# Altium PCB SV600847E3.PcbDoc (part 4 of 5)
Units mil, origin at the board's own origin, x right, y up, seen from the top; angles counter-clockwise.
Board outline 5404 x 2680 mil, 10 copper layers (Top Layer L1, Gnd-Plane - L2, Signals - L3, Gnd-Plane - L4, Pwr Plane - L5, Signals - L6, Gnd-Plane - L7, Signals - L8, Gnd-Plane - L9, Bottom Layer - L10), stack 57.8 mil thick; 517 components, 320 nets, 1784 pads, 1289 vias.
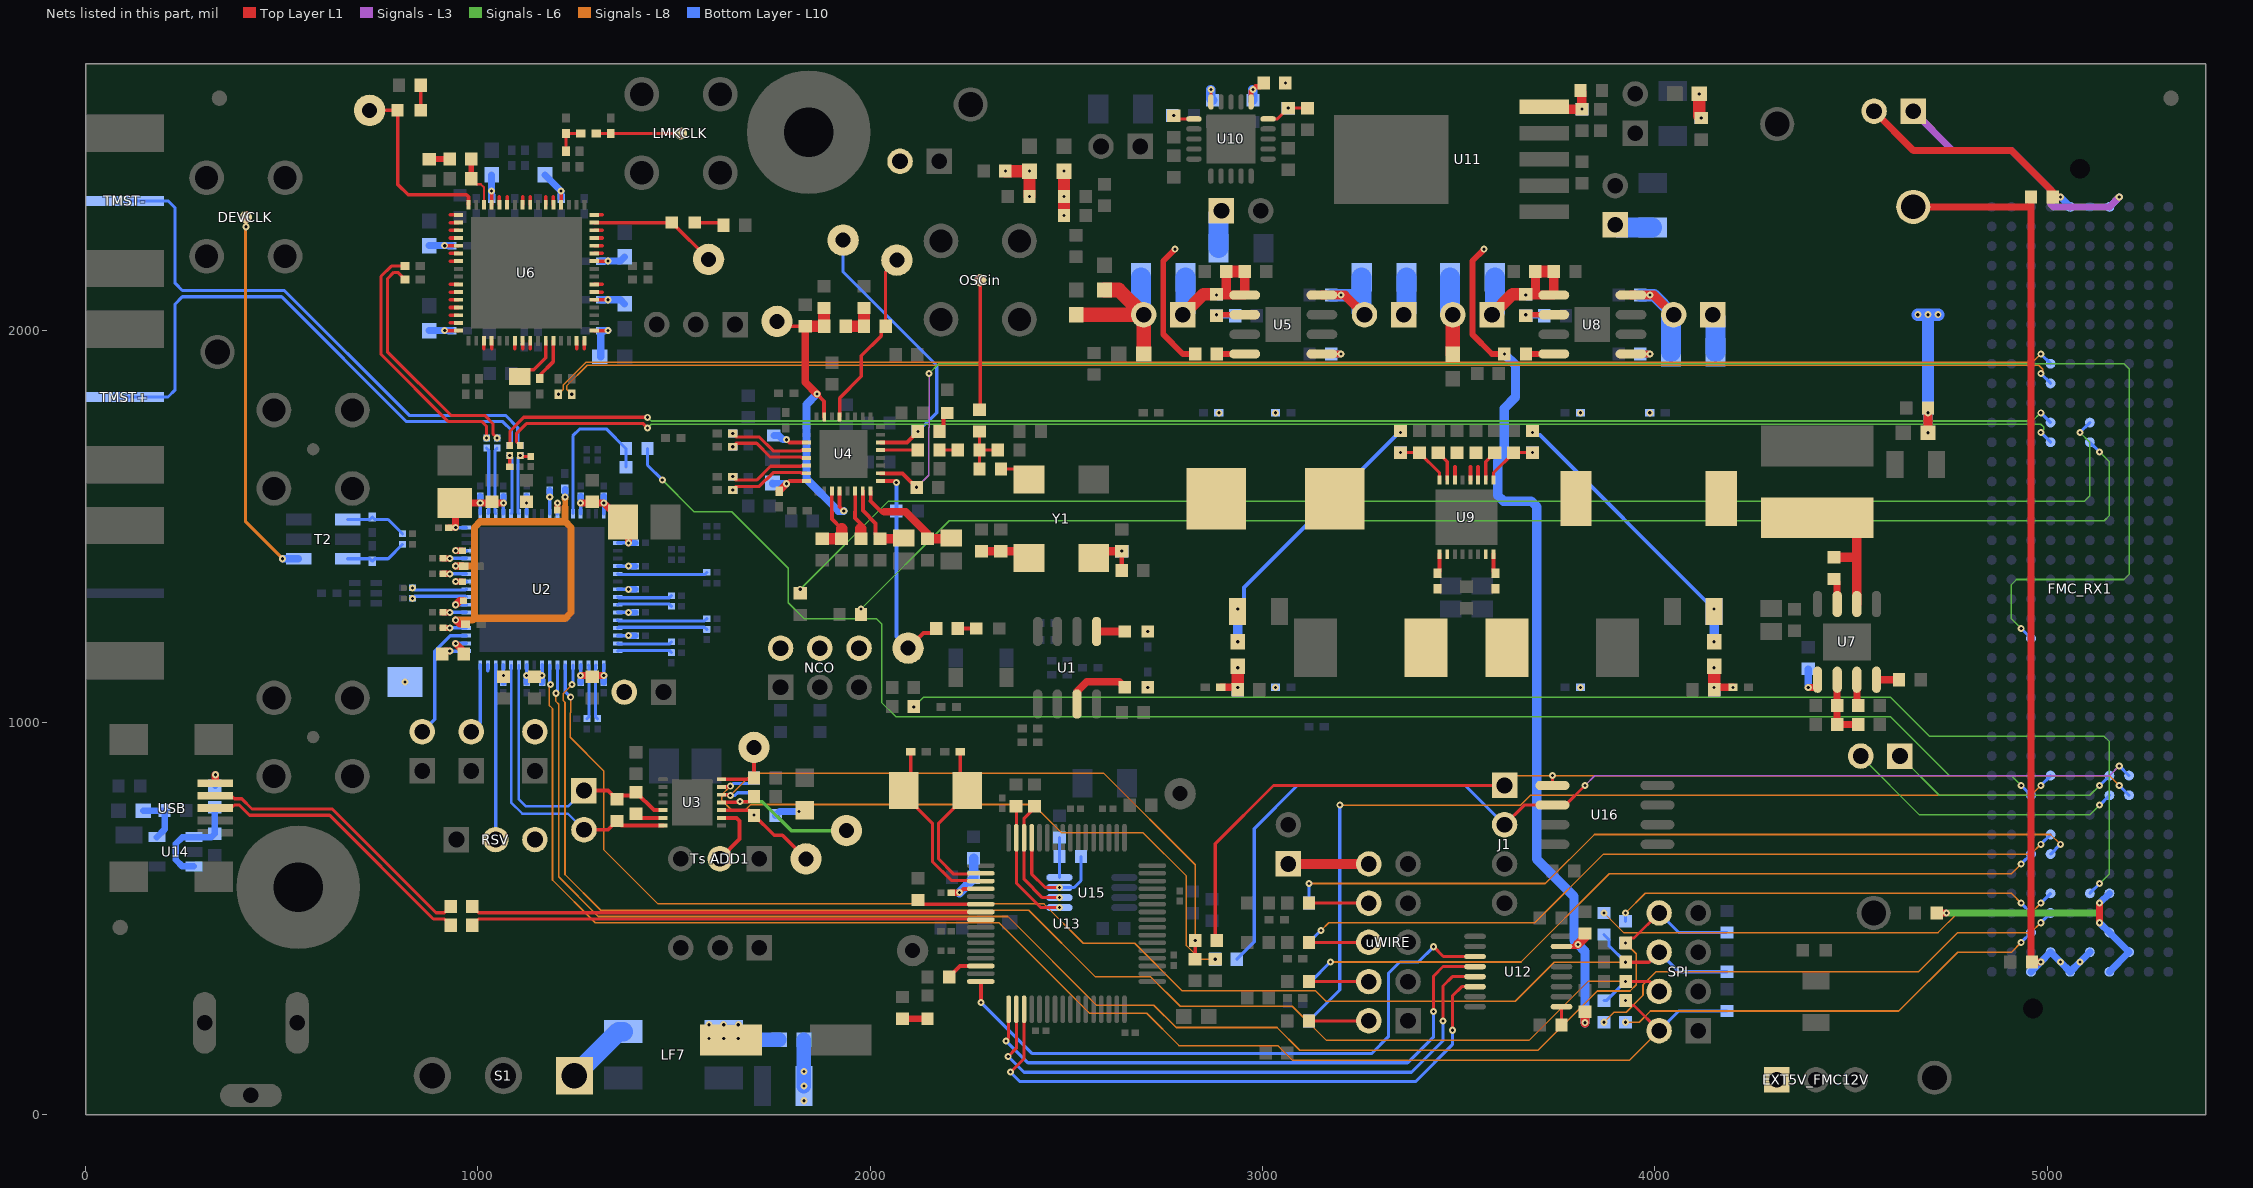
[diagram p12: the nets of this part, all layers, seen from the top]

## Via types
v1: diameter 18, hole 8, Top Layer L1 to Bottom Layer - L10, tented both sides, 1069 vias
v2: diameter 19.68, hole 7.87, Top Layer L1 to Bottom Layer - L10, 95 vias
v3: diameter 18, hole 8, Top Layer L1 to Bottom Layer - L10, tented bottom, 56 vias
v4: diameter 18, hole 8, Top Layer L1 to Bottom Layer - L10, tented top, 54 vias
v5: diameter 25.98, hole 12.99, Top Layer L1 to Bottom Layer - L10, tented top, 8 vias
v6: diameter 19.68, hole 7.87, Top Layer L1 to Bottom Layer - L10, tented top, 5 vias
v7: diameter 126, hole 106, Top Layer L1 to Bottom Layer - L10, tented top, 2 vias

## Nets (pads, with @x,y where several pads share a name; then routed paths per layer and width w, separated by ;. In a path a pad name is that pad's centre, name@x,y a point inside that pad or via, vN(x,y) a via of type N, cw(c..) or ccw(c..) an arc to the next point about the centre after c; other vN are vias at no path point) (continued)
NetC16_2: C16.2 C18.2 C19.2 U2.5 U2.12 U2.29 | length 1287.4
  Top Layer L1 w18: v1(943.26,1261.26) 953.31,1251.21 C18.2@968.57,1251.2 ; v1(943.26,1399.05) C19.2@963.52,1399.05
  Signals - L8 w13: 1222.44,1549.33 v1@1222.44,1570.92
  Signals - L8 w18: v1(943.26,1261.26) 986.22,1261.26 991.14,1266.18 ; v1(943.26,1399.05) 991.14,1399.05 ; 990.79,1497.48 1005.56,1512.24 1222.79,1512.24 ; 991.14,1497.83 991.14,1266.18 ; 1222.44,1549.33 1222.44,1512.59 1237.2,1497.83 1237.2,1280.6 1222.79,1266.18 991.14,1266.18 ; v1@1222.44,1570.92 v1(1222.44,1575.13)
  Bottom Layer - L10 w9: v1(943.26,1261.26) U2.5@970.47,1261.26 ; v1(943.26,1399.05) U2.12@970.47,1399.06 ; U2.29@1222.44,1532.91 v1(1222.44,1575.13)
  Bottom Layer - L10 w16: v1(1222.44,1575.13) C16.2@1222.44,1595.94
NetC17_2: C17.2 U2.41 | length 229.9
  Bottom Layer - L10 w8: U2.41@1356.3,1379.37 1358.14,1377.53 1577.7,1377.53 C17.2@1583.2,1383.03
NetC20_2: C20.2 U2.45 | length 139.9
  Bottom Layer - L10 w8: U2.45@1356.3,1300.63 1358.14,1302.47 1487.7,1302.47 C20.2@1493.2,1296.97
NetC21_2: C21.2 U2.44 | length 139.9
  Bottom Layer - L10 w8: U2.44@1356.3,1320.31 1358.14,1318.47 1487.7,1318.47 C21.2@1493.2,1323.97
NetC22_2: C22.2 R7.2 U2.48 | length 229.9
  Bottom Layer - L10 w8: U2.48@1356.3,1241.57 1358.14,1243.42 1577.7,1243.42 C22.2@1583.2,1237.92
NetC23_2: C23.2 U2.47 | length 229.9
  Bottom Layer - L10 w8: U2.47@1356.3,1261.26 1358.14,1259.42 1577.7,1259.42 C23.2@1583.2,1264.92
NetC26_2: C26.2 R8.2 U2.51 | length 139.9
  Bottom Layer - L10 w8: U2.51@1356.3,1182.52 1358.14,1184.36 1487.7,1184.36 C26.2@1493.2,1178.86
NetC28_2: C28.2 U2.50 | length 139.9
  Bottom Layer - L10 w8: U2.50@1356.3,1202.2 1358.14,1200.36 1487.7,1200.36 C28.2@1493.2,1205.86
NetC29_2: C29.2 R9.2 U2.54 | length 139.9
  Bottom Layer - L10 w8: C29.2@1277.84,1010.19 1283.34,1015.68 1283.34,1145.24 U2.54@1281.5,1147.09
NetC30_2: C30.2 C229.1 T2.4 | length 159.6
  Bottom Layer - L10 w8: T2.4@668.25,1417.95 724.67,1417.95 C229.1@730.85,1411.77 737.03,1417.95 771.09,1417.95 C30.2@807.59,1454.45
NetC31_2: C31.2 U2.53 | length 139.9
  Bottom Layer - L10 w8: U2.53@1301.18,1147.09 1299.34,1145.24 1299.34,1015.69 C31.2@1304.84,1010.19
NetC34_1: C34.1 U3.6 | length 72.4
  Top Layer L1 w10: C34.1@1403.28,767.44 1413.33,757.39 U3.6@1471.47,757.39
NetC34_2: C34.2 C38.2 Tdiode.1 U2.63 U3.5 | length 768.8
  Top Layer L1 w10: Tdiode.1@1270.28,827 1331.84,827 C38.2@1354.28,804.56 1363.72,814 1394.72,814 C34.2@1403.28,822.56 1448.76,777.07 U3.5@1471.47,777.07
  Bottom Layer - L10 w6: U2.63@1104.33,1147.09 1104.33,804.52 1121.5,787.34 1230.62,787.34 Tdiode.1@1270.28,827
NetC36_2: C36.2 C228.1 T2.6 | length 159.6
  Bottom Layer - L10 w8: T2.6@668.25,1517.95 724.67,1517.95 C228.1@730.85,1524.14 737.03,1517.95 771.09,1517.95 C36.2@807.59,1481.45
NetC38_1: C38.1 Tdiode.2 U2.64 U3.7 | length 780.4
  Top Layer L1 w10: Tdiode.2@1270.28,727 1331.84,727 C38.1@1354.28,749.44 1366.02,737.7 U3.7@1471.47,737.7
  Bottom Layer - L10 w6: U2.64@1084.65,1147.09 1084.65,796.36 1113.35,767.66 1229.62,767.66 Tdiode.2@1270.28,727
NetC73_1: C73.1 R24.2 Y1.4 | length 127.8
  Top Layer L1 w22: R24.2@2283.8,1437.44 C73.1@2332.8,1437.44 2386.88,1437.44 Y1.4@2404.32,1420
NetC74_2: C74.2 R26.2 R133.1 Y1.1 | length 126.2
  Top Layer L1 w12.5: R133.1@2641.2,1390 v1(2641.21,1437.44)
  Top Layer L1 w22: Y1.1@2569.68,1420 2587.12,1437.44 v1(2641.21,1437.44)
NetC79_1: C79.1 U4.29 | length 95.2
  Top Layer L1 w8: U4.29@2026.36,1694.8 C79.1@2121.58,1694.8
NetC79_2: C79.2 R29.2 | length 46.6
  Top Layer L1 w8: C79.2@2176.7,1694.8 R29.2@2223.26,1694.8
NetC80_2: C80.2 C81.1 U4.24 | length 273.8
  Top Layer L1 w9: 2000.77,1564.79 U4.24@2000.77,1590.47
  Top Layer L1 w10: 2000.77,1564.79 2029.81,1535.76
  Top Layer L1 w20: 2036.17,1537.88 2089.95,1537.88 2145.86,1481.98 C80.2@2145.86,1468.85
  Top Layer L1 w25: C80.2@2145.86,1468.85 2204.15,1468.85 C81.1@2206.12,1470.82
NetC82_2: C82.2 C83.1 U4.23 | length 201
  Top Layer L1 w10: U4.23@1981.09,1590.47 1981.09,1540.99 2013.9,1508.18 2013.9,1480.28 C82.2@2025.33,1468.85
  Top Layer L1 w25: C82.2@2025.33,1468.85 2083.62,1468.85 C83.1@2085.59,1470.82
NetC84_2: C84.2 U4.22 | length 127.7
  Top Layer L1 w9: 1961.4,1537.61 U4.22@1961.4,1590.47
  Top Layer L1 w10: 1961.4,1537.61 1961.4,1521.7 1976.07,1507.03 1976.07,1494.3
  Top Layer L1 w30: C84.2@1976.07,1468.85 1976.07,1494.3
NetC85_2: C85.2 C87.2 U4.19 | length 181.2
  Top Layer L1 w9: 1902.35,1537.61 U4.19@1902.35,1590.47
  Top Layer L1 w10: 1902.35,1537.61 1902.35,1519.19 1927.24,1494.3
  Top Layer L1 w30: C87.2@1877.54,1468.85 C85.2@1926.81,1468.85 ; C85.2@1927.24,1468.85 1927.24,1494.3
NetC86_1: C86.1 C90.1 C92.1 U4.7 U4.20 Vtune.1 | length 833.6
  Top Layer L1 w8: Vtune.1@1762.39,2023 1774.81,2010.58 C86.1@1834.31,2010.58
  Top Layer L1 w10: v1(1864.03,1838) 1882.66,1819.36 U4.7@1882.66,1779.45 ; U4.20@1922.03,1590.47 1922.03,1550.55 v1@1931.87,1540.71
  Top Layer L1 w20: C86.1@1834.31,2010.58 1834.31,1867.71 v1(1864.03,1838)
  Top Layer L1 w30: C86.1@1834.31,2010.58 C90.1@1882.39,2010.58 C92.1@1882.39,2057.25
  Bottom Layer - L10 w20: v1(1864.03,1838) 1837.39,1811.36 1837.39,1621.05 1918.44,1540 v1(1932.58,1540)
NetC90_2: C90.2 R33.1 R34.2 | length 93.3
  Top Layer L1 w30: C90.2@1937.51,2010.58 R34.2@1984.18,2010.58 R33.1@1984.18,2057.25
NetC93_1: C93.1 U4.11 | length 90.5
  Top Layer L1 w10: v1(1786.92,1721.41) 1793.84,1714.48 U4.11@1837.39,1714.48
  Bottom Layer - L10 w18: C93.1@1754.18,1732.16 1766.84,1732.16 1777.59,1721.41 v1(1786.92,1721.41)
NetC117_1: C117.1 C126.1 C166.1 LMK_LDO.1 R40.1 R41.2 U5.5 | length 443.2
  Top Layer L1 w23.5: C117.1@2883,2092.56 2885.56,2090 U5.5@2954.57,2090 C126.1@2954.57,2150 ; 2907.56,2090 C166.1@2907.56,2150
  Top Layer L1 w31.5: LMK_LDO.1@2797,2040 2849.56,2092.56 C117.1@2880.44,2092.56 ; C166.1@2907.56,2150 C126.1@2954.57,2150
  Bottom Layer - L10 w51: LMK_LDO.1@2797,2040 2804.09,2047.09 R40.1@2804.09,2135.44
  other v1: 2883,2090
NetC117_2: C117.2 R41.1 R49.2 U5.6 | length 120.1
  Top Layer L1 w15: C117.2@2883,2037.44 2885.56,2040 U5.6@2954.57,2040
  Bottom Layer - L10 w15: R41.1@2883,2037.44 R49.2@2930.44,2037.44
  other v1: 2883,2040
NetC122_1: C122.1 U6.11 | length 129.3
  Top Layer L1 w9: C122.1@1106.9,1882.27 1124.37,1899.74 1142.3,1899.74 1172.77,1930.21 U6.11@1172.77,1973.77
NetC123_2: C123.2 R48.1 R50.1 | length 82.6
  Top Layer L1 w8: C123.2@1224.67,2456.69 R50.1@1224.67,2502 R48.1@1261.98,2502
NetC124_1: C124.1 U6.12 | length 110.9
  Top Layer L1 w9: C124.1@1157.3,1877.43 1157.3,1885.74 1192.46,1920.9 U6.12@1192.46,1973.77
NetC127_1: C127.1 LMK_INT.2 R42.2 U5.4 | length 304.5
  Top Layer L1 w23.5: U5.4@3151.43,2090 v1(3199.79,2090) 3210,2090 LMK_INT.2@3260,2040
  Bottom Layer - L10 w31.5: C127.1@3175.05,2090 v1(3199.79,2090) 3252.91,2090
  Bottom Layer - L10 w51: R42.2@3252.91,2134.44 3252.91,2047.09 LMK_INT.2@3260,2040
NetC128_1: C128.1 U5.1 | length 73.1
  Top Layer L1 w18: U5.1@3151.43,1940 v1(3199.8,1940)
  Bottom Layer - L10 w18: C128.1@3175.05,1940 v1(3199.8,1940)
NetC135_1: C135.1 U13.2 Y2.1 | length 435
  Top Layer L1 w8: C135.1@2229.65,926 2229.65,844.53 Y2.1@2247.18,827 2247.18,816.71 2174.47,744 2174.47,652.63 2212.99,614.11 2247.63,614.11 2249.47,615.95 U13.2@2281.97,615.95
NetC137_1: C137.1 U13.3 Y2.2 | length 461.5
  Top Layer L1 w8: C137.1@2103.29,926 2103.29,844.53 Y2.2@2085.76,827 2085.76,816.71 2158.47,744 2158.47,646 2206.36,598.11 2247.63,598.11 2249.47,596.27 U13.3@2281.97,596.27
NetC141_1: C141.1 C142.1 L25.2 U13.4 | length 182.2
  Top Layer L1 w10: v1(2227.5,566.74) 2237.34,576.58 U13.4@2281.97,576.58
  Top Layer L1 w16.5: C142.1@2206.44,566.74 v1(2227.5,566.74)
  Bottom Layer - L10 w24: v1(2227.5,566.74) 2263.56,602.8 C141.1@2263.56,606 L25.2@2263.56,654.44
NetC148_1: C148.1 L8.1 U7.6 | length 378.7
  Top Layer L1 w23.62: L8.1@4414,1522.46 4515,1522.46 U7.6@4515,1302.46 ; C148.1@4457.27,1421.56 4515,1421.56
NetC148_2: C148.2 U7.7 | length 67.2
  Top Layer L1 w18: C148.2@4457.27,1366.44 4465,1358.71 U7.7@4465,1302.46
NetC149_1: C149.1 C150.1 C151.1 LMX_LDO.1 R73.1 R74.2 U8.5 | length 442.2
  Top Layer L1 w23.5: C149.1@3671,2092.56 3673.56,2090 U8.5@3742.57,2090 C151.1@3742.57,2150 ; 3695.56,2090 C150.1@3695.56,2150
  Top Layer L1 w31.5: LMX_LDO.1@3585,2040 3637.56,2092.56 C149.1@3668.44,2092.56 ; C150.1@3695.56,2150 C151.1@3742.57,2150
  Bottom Layer - L10 w51: LMX_LDO.1@3585,2040 3592.09,2047.09 R73.1@3592.09,2134.44
  other v1: 3671,2090
NetC149_2: C149.2 R74.1 R77.2 U8.6 | length 120.1
  Top Layer L1 w15: C149.2@3671,2037.44 3673.56,2040 U8.6@3742.57,2040
  Bottom Layer - L10 w15: R74.1@3671,2037.44 R77.2@3718.44,2037.44
  other v1: 3671,2040
NetC154_1: C154.1 R72.2 R76.2 U7.2 | length 168
  Top Layer L1 w18: U7.2@4465,1109.54 R72.2@4465,995 R76.2@4518.44,995
NetC155_1: C155.1 U7.3 | length 65.5
  Top Layer L1 w18: C155.1@4515,1044 U7.3@4515,1109.54
NetC158_1: C158.1 C159.1 L7.2 LMK_INT.1 LMX_INT.1 R42.1 R75.1 | length 610.3
  Top Layer L1 w24: v1(4696.5,1739.21) C159.1@4696.5,1802
  Bottom Layer - L10 w24: v1(4696.5,1739.21) C158.1@4696.5,1802
  Bottom Layer - L10 w31.5: v1(4670.5,2040) v1(4722.5,2040) ; C158.1@4696.5,1802 v1(4696.5,2040)
  Bottom Layer - L10 w51: LMK_INT.1@3360,2040 3367.09,2047.09 R42.1@3367.09,2134.44 ; LMX_INT.1@4148,2040 4155.09,2032.91 R75.1@4155.09,1945.56
  other v1: 4696.5,1790
NetC160_1: C160.1 LMX_INT.2 R75.2 U8.4 | length 332.3
  Top Layer L1 w23.5: U8.4@3939.43,2090 v1(3987.79,2090) 3998,2090 LMX_INT.2@4048,2040
  Bottom Layer - L10 w31.5: C160.1@3963.05,2090 v1(3987.79,2090) 3998,2090 LMX_INT.2@4048,2040
  Bottom Layer - L10 w51: R75.2@4040.91,1945.56 4040.91,2032.91 LMX_INT.2@4048,2040
NetC161_1: C161.1 U8.1 | length 73.1
  Top Layer L1 w18: U8.1@3939.43,1940 v1(3987.8,1940)
  Bottom Layer - L10 w18: C161.1@3963.05,1940 v1(3987.8,1940)
NetC162_1: C162.1 U7.4 | length 57.4
  Top Layer L1 w18: U7.4@4565,1109.54 C162.1@4622.44,1109.54
NetC168_1: C168.1 R78.2 U9.3 U9.4 U9.6 | length 100.5
  Top Layer L1 w10: U9.6@3490.47,1618.49 3490.47,1652 ; U9.4@3529.84,1618.49 3529.84,1652 ; U9.3@3549.53,1618.49 3549.53,1652
NetC169_1: C169.1 U9.16 | length 50.8
  Top Layer L1 w10: U9.16@3588.9,1429.51 3588.9,1385.53 C169.1@3593.74,1380.68
NetC169_2: C169.2 D11.1 L11.2 U9.15
NetC170_1: C170.1 D12.1 L12.1 U9.10
NetC170_2: C170.2 U9.9 | length 50.8
  Top Layer L1 w10: C170.2@3446.26,1380.69 3451.1,1385.53 U9.9@3451.1,1429.51
NetC174_1: C174.1 R81.2 R86.2 U9.1 | length 139.1
  Top Layer L1 w8: U9.1@3588.9,1618.49 3588.9,1637.34 R86.2@3640,1688.44 v1(3688,1688.44)
NetC175_2: C175.2 R82.1 R87.2 U9.8 | length 139.1
  Top Layer L1 w8: v1(3352,1688.44) R87.2@3400,1688.44 3451.1,1637.34 U9.8@3451.1,1618.49
NetC178_1: C178.1 U9.2 | length 79.4
  Top Layer L1 w8: U9.2@3569.21,1618.49 3569.21,1665.65 C178.1@3592,1688.44
NetC179_1: C179.1 U9.7 | length 79.4
  Top Layer L1 w8: C179.1@3448,1688.44 3470.79,1665.65 U9.7@3470.79,1618.49
NetC186_1: C186.1 R79.1 R90.2 U10.10 | length 111.9
  Top Layer L1 w8: U10.10@3014.16,2539.18 3038.3,2539.18 v1(3065.68,2566.56) R79.1@3114.68,2566.56
NetC187_1: C187.1 U10.15 | length 61.2
  Top Layer L1 w8: U10.15@2868.49,2582.49 v1(2868.49,2614.17)
  Bottom Layer - L10 w24: v1(2868.49,2614.17) 2868.49,2590.61 C187.1@2872.67,2586.43
NetC192_2: C192.2 R93.1 R96.2 U11.5 | length 147.7
  Top Layer L1 w24: U11.5@3718.22,2569.86 3724.13,2563.95 v1(3814,2563.95) 3814,2608.44 R96.2@3810.44,2612
NetC193_1: C193.1 L17.1 LF7.3 | length 150.4
  Bottom Layer - L10 w37: LF7.3@1626.46,212.6 1657.4,212.6 1678.4,191.6 L17.1@1768.16,191.6
  other v1: 1589.24,195.07 1626.46,195.07 1663.67,195.07 1589.24,230.12 1626.46,230.12 1663.67,230.12
NetC194_1: C194.1 EXT5V_FMC12V.1 L17.2 | length 118.1
  Bottom Layer - L10 w37: v1(1831.15,73.49) L17.2@1831.15,191.6
  other v1: 1831.15,36.28 1831.15,110.7
NetC201_1: C201.1 R103.2 U14.1 U14.3 | length 271.6
  Bottom Layer - L10 w16.5: U14.3@275.94,633.46 246.64,633.46 229.76,650.33 229.76,691.39 246.64,708.26 U14.1@275.94,708.26 320.38,708.26 C201.1@329.24,717.12 R103.2@329.24,784.4
NetC211_1: C211.1 L26.1 U14.5 | length 130.2
  Bottom Layer - L10 w16.5: L26.1@146.73,775.86 C211.1@201.14,775.86 201.14,727.95 U14.5@181.46,708.26
NetC213_2: C213.2 L1.2 U4.16 | length 118.1
  Top Layer L1 w10: v1(1786.92,1609.14) 1793.84,1616.06 U4.16@1837.39,1616.06
  Top Layer L1 w18: C213.2@1767.87,1590.09 v1(1786.92,1609.14)
  Bottom Layer - L10 w18: L1.2@1751,1611 1751,1609.14 v1(1786.92,1609.14)
NetDEVCLK_1: DEVCLK.1 T2.3 | length 951.6
  Top Layer L1 w8: v1(408.31,2264.25) DEVCLK.1@408.31,2289
  Signals - L8 w8: v1@407.71,2264.25 407.71,1512.24 v1@502,1417.95
  Bottom Layer - L10 w18: v1(501.57,1417.95) T2.3@543.06,1417.95
NetFLout_1: FLout.1 R34.1 U4.5 | length 459.7
  Top Layer L1 w8: R34.1@2039.3,2010.58 2039.3,2150.3 FLout.1@2068,2179
  Top Layer L1 w9: U4.5@1922.03,1779.8 1922.03,1827.59 1977.48,1883.04 1977.48,1935.36 2028.04,1985.92 2028.04,1999.32 R34.1@2039.3,2010.58
NetFMC_RX1_C30: FMC_RX1.C30 J1.2 R127.2 U16.6 | length 2740.7
  Top Layer L1 w8: J1.2@3617,740 3667,790 U16.6@3739.14,790 3772.2,790 v1(3822.2,840)
  Signals - L3 w4: v1(3822.2,840) 3847.2,865 5159,865 v3(5184,890)
  Bottom Layer - L10 w8: R127.2@2934.68,397.13 2979,441.45 2979,730 3089,840 3517,840 J1.2@3617,740 ; v3(5184,890) FMC_RX1.C30@5209,865
NetFMC_RX1_C31: FMC_RX1.C31 J1.1 R126.2 U16.5 | length 2693.6
  Top Layer L1 w8: R126.2@2879.56,445 2879.56,691.56 3028,840 J1.1@3617,840 ; U16.5@3739.14,840 v1(3739.14,865)
  Signals - L8 w4: J1.1@3617,840 3642,865 5159,865 v3(5184,840)
  Bottom Layer - L10 w8: v3(5184,840) FMC_RX1.C31@5209,815
NetFMC_RX1_C39: FMC_RX1.C39 FMC_RX1.D36 FMC_RX1.D38 FMC_RX1.D40 R132.2 | length 727.6
  Top Layer L1 w18: R132.2@4718.56,515 v1(4743.31,515) ; v1(5134,490) v1(5134,540)
  Signals - L6 w18: v1(4743.31,515) 5134,515 ; v1(5134,490) v1(5134,540)
  Bottom Layer - L10 w18: v1(5134,490) FMC_RX1.D38@5159,465 FMC_RX1.C39@5209,415 FMC_RX1.D40@5159,365 ; v1(5134,540) FMC_RX1.D36@5159,565
NetFMC_RX1_D30: "KC705 JTAG.1" FMC_RX1.D30 | length 596.1
  Signals - L6 w4: 4625,915 4725,815 5109,815 v3(5134,840)
  Bottom Layer - L10 w8: v3(5134,840) FMC_RX1.D30@5159,865
NetFMC_RX1_D31: "KC705 JTAG.2" FMC_RX1.D31 | length 716.8
  Signals - L6 w4: 4525,915 4675,765 5109,765 v3(5134,790)
  Bottom Layer - L10 w8: v3(5134,790) FMC_RX1.D31@5159,815
NetFMC_RX1_E12: FMC_RX1.E12 R136.2 | length 3593.8
  Signals - L6 w4: v1(1821.5,1340) 2046.5,1565 5096,1565 5109,1578 5109,1715 v3(5084,1740)
  Bottom Layer - L10 w8: v3(5084,1740) FMC_RX1.E12@5109,1765
NetFMC_RX1_E13: FMC_RX1.E13 R137.2 | length 3488.7
  Signals - L6 w4: v1(1976.62,1290) 2201.62,1515 5146,1515 5159,1528 5159,1665 v3(5134,1690)
  Bottom Layer - L10 w8: FMC_RX1.E13@5109,1715 v3(5134,1690)
NetFMC_RX1_E36: FMC_RX1.E36 R138.2 | length 3512.8
  Signals - L6 w4: v1(2111.06,1040) 2136.06,1065 4601,1065 4701,965 5146,965 5159,952 5159,615 v3(5134,590)
  Bottom Layer - L10 w8: FMC_RX1.E36@5109,565 v3(5134,590)
NetFMC_RX1_G30: FMC_RX1.G30 R121.2 | length 2425
  Signals - L8 w4: v1@3197.99,789.01 3657.01,789.01 3683,815 4959,815 v3(4984,840)
  Bottom Layer - L10 w8: R121.2@3118.56,240 3197,318.44 v1(3197,790) ; v3(4984,840) FMC_RX1.G30@5009,865
NetFMC_RX1_G33: FMC_RX1.G33 R69.2 | length 2004.3
  Signals - L8 w4: v1(3149,470.44) 3168.56,490 3694,490 3869,665 4959,665 v3(4984,690)
  Bottom Layer - L10 w8: R69.2@3118.56,440 v1(3149,470.44) ; v3(4984,690) FMC_RX1.G33@5009,715
NetFMC_RX1_G34: FMC_RX1.G34 R119.2 | length 2062.9
  Signals - L8 w4: v1(3118.56,590) 3721,590 3846,715 5009,715 v3(5034,690)
  Bottom Layer - L10 w8: R119.2@3118.56,540 v1(3118.56,590) ; FMC_RX1.G34@5009,665 v3(5034,690)
NetFMC_RX1_G36: FMC_RX1.G36 R57.2 | length 1200.7
  Signals - L8 w4: v1(3870.44,515) 3920.44,465 4722,465 4772,515 4959,515 v3(4984,540)
  Bottom Layer - L10 w8: v3(4984,540) FMC_RX1.G36@5009,565
NetFMC_RX1_G37: FMC_RX1.G37 R55.2 | length 1269.8
  Signals - L8 w4: v1(3870.44,236.38) 3896.06,262 3927,262 3970,305 3970,332 4003,365 4672,365 4772,465 4959,465 v3(4984,490)
  Bottom Layer - L10 w8: v3(4984,490) FMC_RX1.G37@5009,515
NetFMC_RX1_H23: FMC_RX1.H23 R46.1 U4.26 | length 4477.4
  Top Layer L1 w10: U4.26@2026.36,1635.74 2082.5,1635.74 2086.5,1631.74 v1(2118.23,1600.02)
  Signals - L3 w4: v1(2118.23,1600.02) 2149.14,1630.92 2149.14,1752.14 2151,1754 v1@2151,1890
  Signals - L6 w4: v1(2150,1890) 2175,1915 5196,1915 5209,1902 5209,1378 5196,1365 4922,1365 4909,1352 4909,1265 v3(4934,1240)
  Bottom Layer - L10 w8: v3(4934,1240) FMC_RX1.H23@4959,1215
NetFMC_RX1_H34: FMC_RX1.H34 R120.2 | length 1975.1
  Signals - L8 w4: v1(3173,390) 3659,390 3884,615 4909,615 v3(4934,640)
  Bottom Layer - L10 w8: R120.2@3118.56,340 3123,340 v1(3173,390) ; v3(4934,640) FMC_RX1.H34@4959,665
NetFMC_RX1_H37: FMC_RX1.H37 R58.2 | length 1096.2
  Signals - L8 w4: v1(3925.56,515) 3975.56,565 4909,565 v3(4934,540)
  Bottom Layer - L10 w8: R58.2@3925.56,493.62 v1(3925.56,515) ; v3(4934,540) FMC_RX1.H37@4959,515
NetFMC_RX1_H38: FMC_RX1.H38 R54.2 | length 1128.1
  Signals - L8 w4: v1(3925.56,236.38) 3960.38,236.38 3989,265 4622,265 4772,415 4909,415 v3(4934,440)
  Bottom Layer - L10 w8: v3(4934,440) FMC_RX1.H38@4959,465
NetJ3_1: J3.1 uWIRE.10 | length 205
  Top Layer L1 w25: J3.1@3066,640 uWIRE.10@3271,640
NetL6_1: L6.1 LMX_LDO.2 R73.2 | length 197.9
  Top Layer L1 w37: L6.1@3485,1939.5 LMX_LDO.2@3485,2040
  Bottom Layer - L10 w51: R73.2@3477.91,2134.44 3477.91,2047.09 LMX_LDO.2@3485,2040
NetL9_1: L9.1 L10.1 L13.1 LMK_LDO.2 R40.2 | length 496.5
  Top Layer L1 w37: L13.1@2525,2040 LMK_LDO.2@2697,2040 ; L10.1@2597,2103 2634,2103 LMK_LDO.2@2697,2040 ; L9.1@2697,1940 LMK_LDO.2@2697,2040
  Bottom Layer - L10 w51: R40.2@2689.91,2135.44 2689.91,2047.09 LMK_LDO.2@2697,2040
NetLD1_1: LD1.1 Status1.1 U6.31 | length 330.1
  Top Layer L1 w9: U6.31@1296.79,2274.95 Status1.1@1493.98,2274.95 LD1.1@1587.93,2181
NetLD2_1: LD2.1 Status2.1 U6.48 | length 473.5
  Top Layer L1 w9: LD2.1@724,2561 Status2.1@794.71,2561 ; Status2.1@795,2561 795,2373 822,2346 970.65,2346 975.92,2340.73 U6.48@975.92,2320.23
NetLD_1: LD.1 R100.2 | length 46.9
  Top Layer L1 w10: R100.2@2223.06,1240 LD.1@2269.98,1240
NetLF1_1: LF1.1 LF2.1 U6.46 | length 136.1
  Top Layer L1 w5.5: LF2.1@982.86,2386.74 996.86,2372.74 1007.3,2372.74 1015.29,2364.75 U6.46@1015.29,2320.23
  Top Layer L1 w15: LF2.1@982.86,2386.74 LF1.1@982.86,2436.74
NetLF1_2: LF1.2 LF3.2 | length 51.9
  Top Layer L1 w15: LF3.2@875.86,2436.74 LF1.2@927.74,2436.74
NetLF7_2: LF7.2 S1.1 | length 171
  Bottom Layer - L10 w50: S1.1@1246.1,100.2 1358.5,212.6 LF7.2@1370.55,212.6
NetLMKCLK_1: LMKCLK.1 R48.2 R51.2 | length 216.1
  Top Layer L1 w8: R48.2@1301.36,2502 R51.2@1338.67,2502 LMKCLK.1@1517.5,2502
NetMUX_1: MUX.1 R99.1 R143.1 U4.30 | length 713.1
  Top Layer L1 w10: U4.30@2026.36,1714.48 2093.87,1714.48 v1(2121.58,1742.19)
  Bottom Layer - L10 w8: MUX.1@1931,2230 1931,2149 2169.5,1910.5 2169.5,1790.12 v1(2121.58,1742.19)
NetMUXout_1: MUXout.1 R99.2 | length 55.5
  Top Layer L1 w10: R99.2@2176.7,1742.19 2186.5,1752 2186.5,1779.47 MUXout.1@2196.5,1789.47
NetOR_T0_1: OR_T0.1 U1.1 | length 71.5
  Top Layer L1 w19.5: U1.1@2577,1232.52 OR_T0.1@2648.47,1232.52
NetOR_T0_2: OR_T0.2 R2.1
  other v1: 2707.53,1232.52
NetOR_T1_1: OR_T1.1 U1.7 | length 169.1
  Top Layer L1 w19.5: U1.7@2527,1047.48 2527,1079 2552,1104 2634.47,1104 OR_T1.1@2648.47,1090
NetOR_T1_2: OR_T1.2 R10.1
  other v1: 2707.53,1090
NetOSCin_1: OSCin.1 R25.2 | length 323.6
  Top Layer L1 w8: R25.2@2280.38,1804.45 OSCin.1@2280.38,2128
NetR13_1: R13.1 U2.2 | length 62.9
  Top Layer L1 w18: v1(943.26,1202.2) 963.82,1181.65 R13.1@963.82,1175
  Bottom Layer - L10 w9: v1(943.26,1202.2) U2.2@970.47,1202.2
NetR13_2: R13.2 U2.1 | length 64.9
  Top Layer L1 w18: R13.2@908.7,1175 916.22,1182.52 v1(928.26,1182.52)
  Bottom Layer - L10 w9: v1(928.26,1182.52) U2.1@970.47,1182.52
NetR17_2: R17.2 TEMP.2 | length 63.6
  Bottom Layer - L10 w18: R17.2@1758.84,763.41 1768.84,773.41 v1(1818.28,773.41)
NetR25_1: R25.1 R27.1 R28.2 R29.1 | length 142.8
  Top Layer L1 w8: R27.1@2278.38,1646.56 R29.1@2278.38,1694.8 ; R25.1@2278.38,1742.44 R29.1@2278.38,1694.8 ; R28.2@2325.26,1694.8 R29.1@2278.38,1694.8
NetR27_2: R27.2 Y1.3 | length 81.8
  Top Layer L1 w8: R27.2@2333.5,1646.56 2377.76,1646.56 Y1.3@2404.32,1620
NetR31_1: R31.1 R124.1 R126.1 U3.12 | length 1637
  Top Layer L1 w8: R124.1@2828,397.13 2828.44,397.57 v1(2828.44,445)
  Top Layer L1 w9: U3.12@1621.08,816.44 1641.28,816.44 v1(1643.28,814.44)
  Signals - L8 w4: v1(1643.28,814.44) 1700.46,871.62 2594.38,871.62 2828.44,637.56 v1(2828.44,445)
  Bottom Layer - L10 w8: v1(1643.28,814.44) 1654.96,814.44 1661.99,821.47 1693.66,821.47 R31.1@1703.72,811.41
NetR32_1: R32.1 R125.1 R127.1 U3.13 | length 1677.8
  Top Layer L1 w9: U3.13@1621.08,836.13 1641.28,836.13 v1(1643.28,838.13)
  Signals - L8 w4: v1(1643.28,838.13) 1621.08,815.93 1621.08,802.92 1646,778 1682,778 1695.44,791.44 2415.89,791.44 2488.33,719 2696,719 2806,609 2806,432 2840.87,397.13 v1(2879.56,397.13)
  Bottom Layer - L10 w8: v1(1643.28,838.13) 1650.15,845 1689.91,845 R32.1@1703.72,858.81
NetR39_2: R39.2 U5.8 | length 71
  Top Layer L1 w15: R39.2@2883.56,1940 U5.8@2954.57,1940
NetR45_2: R45.2 Status2.2 | length 63.7
  Top Layer L1 w9: Status2.2@854.05,2561.29 R45.2@854.06,2625
NetR52_1: R52.1 USB.2 | length 729.7
  Top Layer L1 w8: USB.2@330.71,813.93 371.71,813.93 379.46,806.18 397.98,806.18 424.17,780 628.63,780 892.94,515.69 914.24,515.69 R52.1@930.24,531.69
NetR52_2: R52.2 U13.7 | length 1304
  Top Layer L1 w8: R52.2@985.36,531.69 1001.36,515.69 2247.63,515.69 2249.47,517.53 U13.7@2281.97,517.53
NetR53_1: R53.1 USB.3 | length 729.7
  Top Layer L1 w8: USB.3@330.71,782.44 371.71,782.44 379.46,790.18 391.36,790.18 417.54,764 622,764 886.31,499.69 914.24,499.69 R53.1@930.24,483.69
NetR53_2: R53.2 U13.8 | length 1304
  Top Layer L1 w8: R53.2@985.36,483.69 1001.36,499.69 2247.63,499.69 2249.47,497.84 U13.8@2281.97,497.84
NetR54_1: R54.1 R118.1 R139.2 SPI.2 U2.59 | length 3907.1
  Top Layer L1 w8: v1(3925.56,291.5) 3938.06,279 3947,279 SPI.2@4011,215
  Signals - L8 w4: v1(1185.19,1097) 1182,1093.81 1182,1044 1190,1036 1190,599 1299,490 2328,490 2559,259 2705,259 2787,177 3039,177 3076,140 3936,140 SPI.2@4011,215
  Bottom Layer - L10 w8: U2.59@1183.07,1147.09 1183.07,1099.12 v1(1185.19,1097) ; SPI.2@4011,215 4061,265 R139.2@4184.44,265
NetR55_1: R55.1 R110.1 SPI.4 U2.56 | length 3659.1
  Top Layer L1 w8: v1(3925.56,340.5) 3985.5,340.5 SPI.4@4011,315
  Signals - L8 w4: v1(1240,1097) 1217,1074 1217,1057 1222,1052 1222,613 1313,522 2404,522 2574,352 2715,352 2790,277 3076,277 3163,190 3679.36,190 3829.86,340.5 v1(3925.56,340.5)
  Bottom Layer - L10 w8: v1(1240,1097) 1242.13,1099.12 U2.56@1242.13,1147.09 ; R55.1@3870.44,291.5 3876.56,291.5 v1(3925.56,340.5)
NetR56_2: R56.2 Status1.2 | length 72.9
  Top Layer L1 w9: Status1.2@1553.03,2274.95 R56.2@1625.94,2274.95
NetR57_1: R57.1 R111.1 R140.2 SPI.6 U2.57 | length 3702.1
  Top Layer L1 w8: v1(3925.56,389.5) 3985.5,389.5 SPI.6@4011,415
  Signals - L8 w4: v1(1236.44,1065) 1236.44,1026.44 1235,1025 1235,963 1320.28,877.72 1320.28,676.72 1459,538 2443,538 2543,438 2674,438 2795,317 3135,317 3162,290 3644,290 3743.5,389.5 v1(3925.56,389.5)
  Bottom Layer - L10 w8: U2.57@1222.44,1147.09 1222.44,1079 v1(1236.44,1065) ; R57.1@3870.44,459.88 3883,447.32 3883,432.06 v1(3925.56,389.5) ; SPI.6@4011,415 4061,365 R140.2@4184.44,365
NetR58_1: R58.1 R109.1 R141.2 SPI.8 U2.58 | length 3973.1
  Top Layer L1 w8: v1(3925.56,438.5) 3938.06,451 3947,451 SPI.8@4011,515
  Signals - L8 w4: v1(1198.76,1075) 1198.76,1054.24 1206,1047 1206,607 1307,506 2351,506 2577,280 2723,280 2780,223 3037,223 3095,165 3702,165 3853,316 3937,316 3953,332 3953,411.06 v1(3925.56,438.5)
  Bottom Layer - L10 w8: v1(1198.76,1075) 1202.76,1079 U2.58@1202.76,1147.09 ; SPI.8@4011,515 4061,465 R141.2@4184.44,465
NetR65_2: R65.2 U12.9 | length 47
  Top Layer L1 w8: R65.2@3762.24,229 U12.9@3762.24,275.96
NetR66_1: R66.1 U13.14 | length 92.5
  Top Layer L1 w10: R66.1@2201.03,351.73 2229.03,379.73 U13.14@2281.97,379.73
NetR67_2: R67.2 U13.6 | length 164.9
  Top Layer L1 w10: R67.2@2121.47,547.96 2132.22,537.21 U13.6@2281.97,537.21
NetR70_2: R70.2 U7.1 | length 71.1
  Top Layer L1 w18: v1(4391.19,1090) U7.1@4415,1090
  Bottom Layer - L10 w18: v1(4391.19,1090) R70.2@4391.19,1137.29
NetR71_2: R71.2 U8.8 | length 71
  Top Layer L1 w15: R71.2@3671.56,1940 U8.8@3742.57,1940
NetR80_2: R80.2 R89.2 U10.11 | length 96
  Top Layer L1 w13.5: U10.11@2970.86,2582.49 2970.86,2609.67 v1(2975.36,2614.17) 2982.18,2621 2993.1,2621 R80.2@3003.1,2631
  Bottom Layer - L10 w24: R89.2@2975.36,2586.43 v1(2975.36,2614.17)
NetR85_1: R85.1 R88.2 U10.16 | length 55
  Top Layer L1 w8: v1(2773.68,2547.56) 2782.05,2539.18 U10.16@2825.19,2539.18
NetR97_2: R97.2 uWIRE.8 | length 152.4
  Top Layer L1 w8: R97.2@3118.56,540 uWIRE.8@3271,540
NetR98_2: R98.2 uWIRE.6 | length 152.4
  Top Layer L1 w8: R98.2@3118.56,440 uWIRE.6@3271,440
NetR100_1: R100.1 R142.1 TP_LD.1 U4.25 | length 568.4
  Top Layer L1 w10: U4.25@2026.36,1616.06 2062.5,1616.06 v1(2066.5,1612.06) ; TP_LD.1@2096.5,1190 2135.5,1229 2156.94,1229 R100.1@2167.94,1240
  Bottom Layer - L10 w10: v1(2066.5,1612.06) 2066.5,1220 TP_LD.1@2096.5,1190
NetR101_2: R101.2 uWIRE.4 | length 152.4
  Top Layer L1 w8: R101.2@3118.56,340 uWIRE.4@3271,340
NetR102_2: R102.2 uWIRE.2 | length 152.4
  Top Layer L1 w8: R102.2@3118.56,240 uWIRE.2@3271,240
NetR103_1: R103.1 USB.1 | length 49.6
  Top Layer L1 w19.5: USB.1@330.71,845.43 v1(330.71,867.27)
  Bottom Layer - L10 w16.5: R103.1@330.71,839.52 v1(330.71,867.27)
NetR105_1: R105.1 R108.2 U15.4 | length 102.1
  Bottom Layer - L10 w8: U15.4@2482.32,605.39 R108.2@2482.32,659 R105.1@2482.32,707.44
NetR106_1: R106.1 U13.62 U15.2 | length 307.2
  Top Layer L1 w8: R106.1@2419.2,787.44 2419.2,783.44 2392.2,756.44 U13.62@2392.2,706.5 2392.2,600.8 2438.8,554.2 v1(2482.32,554.2)
NetR107_1: R107.1 U13.63 U15.1 | length 332.3
  Top Layer L1 w8: R107.1@2371.2,787.44 2372.52,786.13 U13.63@2372.52,706.5 2372.52,591.48 2435.39,528.61 v1(2482.32,528.61)
NetR108_1: R108.1 U13.61 U15.3 | length 301
  Top Layer L1 w8: U13.61@2411.89,706.5 2411.89,614.11 2446.2,579.8 v1(2482.32,579.8)
  Bottom Layer - L10 w8: v1(2482.32,579.8) 2519.8,579.8 2537.44,597.44 R108.1@2537.44,659
NetR112_2: R112.2 USB_PWR.2 | length 64
  Top Layer L1 w16.5: R112.2@2081.91,245.68 USB_PWR.2@2145.91,245.68
NetR134_2: R134.2 R135.2 U2.30 | length 408.9
  Bottom Layer - L10 w8: U2.30@1242.13,1532.91 1242.13,1731.13 1260,1749 1327.24,1749 R134.2@1377.24,1699 R135.2@1377.24,1651.56
NetRSV_2: RSV.2 U2.66 | length 445.1
  Bottom Layer - L10 w9: RSV.2@1045.28,702 U2.66@1045.28,1147.09
"NetTs ADD1_2": "Ts ADD1.2" U3.9 | length 166.4
  Top Layer L1 w10: 1617.28,653 1667.28,703 1667.28,749 1658.89,757.39 U3.9@1621.08,757.39
NetU2_3: U2.3 Vcmo.2 | length 315.6
  Bottom Layer - L10 w9: Vcmo.2@857.78,977 890,1009.22 890,1182.5 929.39,1221.89 U2.3@970.47,1221.89
NetU2_68: U2.68 Vbg.2 | length 179.7
  Bottom Layer - L10 w9: Vbg.2@982.78,977 1005.91,1000.13 U2.68@1005.91,1147.09
NetU12_3: U12.3 U13.16 | length 1584.7
  Top Layer L1 w8: v1(3436.14,428.91) 3461.14,403.91 U12.3@3541.76,403.91
  Top Layer L1 w10: v1(2281.97,287) U13.16@2281.97,340.36
  Bottom Layer - L10 w8: v1(2281.97,287) 2411.97,157 3279,157 3321,199 3321,360.71 3350.29,390 3397.23,390 v1(3436.14,428.91)
NetU12_4: U12.4 U13.17 | length 1495
  Top Layer L1 w8: v1(2345.83,189.03) 2352.83,196.03 U13.17@2352.83,269.5 ; v1(3436.14,264) 3436.14,354.32 3460.14,378.32 U12.4@3541.76,378.32
  Bottom Layer - L10 w8: v1(2345.83,189.03) 2401.86,133 3370,133 3436.14,199.14 v1(3436.14,264)
NetU12_5: U12.5 U13.18 | length 1542.4
  Top Layer L1 w8: v1(2351.68,149.19) 2372.52,170.03 U13.18@2372.52,269.5 ; v1(3460.14,240) 3460.14,328.73 3484.14,352.73 U12.5@3565.76,352.73
  Bottom Layer - L10 w8: v1(2351.68,149.19) 2391.86,109 3379.94,109 3460.14,189.2 v1(3460.14,240)
NetU12_6: U12.6 U13.19 | length 1541.7
  Top Layer L1 w8: v1(2357.52,109.34) 2392.2,144.03 U13.19@2392.2,269.5 ; v1(3484.14,216) 3484.14,303.14 3508.14,327.14 U12.6@3541.76,327.14
  Bottom Layer - L10 w8: v1(2357.52,109.34) 2381.86,85 3389.88,85 3484.14,179.26 v1(3484.14,216)
PG_C2M_RX: FMC_RX1.D1 PG_RX1.1 | length 692.9
  Signals - L3 w18: PG_RX1.1@4659,2559 4759,2459 4909,2459 5009,2359 5009,2323 5017,2315 5159,2315 v3(5184,2340)
  Bottom Layer - L10 w18: FMC_RX1.D1@5159,2315 v3(5184,2340)
PG_M2C_RX: FMC_RX1.F1 PG_RX1.2 RR6.1 | length 609.2
  Top Layer L1 w18: PG_RX1.2@4559,2559 4659,2459 4909,2459 5014.12,2353.88 RR6.1@5014.12,2340 v1(5034,2340)
  Bottom Layer - L10 w18: v1(5034,2340) FMC_RX1.F1@5059,2315
RFOUTA_N: C96.1 R38.2 U4.13 | length 206.9
  Top Layer L1 w8: v4(1649.59,1703.27) 1658.59,1712.27 1710.4,1712.27 1745.71,1676.96 1823.54,1676.96 1825.39,1675.11 U4.13@1837.39,1675.11
RFOUTA_P: C101.2 R37.1 U4.12 | length 206.9
  Top Layer L1 w8: v4(1649.59,1737.27) 1658.59,1728.27 1717.02,1728.27 1752.34,1692.96 1823.54,1692.96 1825.39,1694.8 U4.12@1837.39,1694.8
RFOUTB_N: C100.2 R36.2 U4.15 | length 206.9
  Top Layer L1 w8: v4(1649.59,1593.27) 1658.59,1602.27 1717.02,1602.27 1752.34,1637.59 1823.54,1637.59 1825.39,1635.74 U4.15@1837.39,1635.74
RFOUTB_P: C97.1 R35.1 U4.14 | length 206.9
  Top Layer L1 w8: v4(1649.59,1627.27) 1658.59,1618.27 1710.4,1618.27 1745.71,1653.59 1823.54,1653.59 1825.39,1655.43 U4.14@1837.39,1655.43
SYNC_N: FMC_RX1.G13 R20.2 | length 4000.8
  Top Layer L1 w8: R20.2@1107,1707.98 1098,1716.98 1098,1737 1123.5,1762.5 1421.55,1762.5 v1(1432.55,1751.5)
  Signals - L6 w4: v1(1432.55,1751.5) 1442.05,1761 4984,1761 4992,1753 4992,1748 v3(4984,1740)
  Bottom Layer - L10 w8: v3(4984,1740) FMC_RX1.G13@5009,1715
SYNC_P: FMC_RX1.G12 R19.2 | length 4000.9
  Top Layer L1 w8: R19.2@1080,1707.98 1082,1709.98 1082,1743.63 1116.87,1778.5 v1(1432.55,1778.5)
  Signals - L6 w4: v1(1432.55,1778.5) 1442.05,1769 4963,1769 v3(4984,1790)
  Bottom Layer - L10 w8: v3(4984,1790) FMC_RX1.G12@5009,1765
SYNC_SE: FMC_RX1.H31 R134.1 | length 4086.6
  Signals - L6 w4: v1(1470,1619) 1551,1538 1647,1538 1791,1394 1791,1306 1832,1265 2016,1265 2029,1252 2029,1051.5 2065.5,1015 4601,1015 4751,865 4909,865 v3(4934,840)
  Bottom Layer - L10 w8: R134.1@1432.36,1699 1432.36,1656.64 v1(1470,1619) ; v3(4934,840) FMC_RX1.H31@4959,815
SYNC~/TMST_N: R20.1 R21.1 R23.1 U2.23 | length 178.8
  Top Layer L1 w8: R20.1@1107.99,1681.01 1110.01,1678.99 R23.1@1135,1678.99
  Bottom Layer - L10 w8: U2.23@1104.33,1532.91 1102.49,1534.76 1102.49,1675.32 v1(1107.99,1680.82)
SYNC~/TMST_P: R18.1 R19.1 R22.1 U2.22 | length 179
  Top Layer L1 w8: R22.1@1081.01,1653 R19.1@1080.99,1681.01
  Bottom Layer - L10 w8: v1(1080.99,1680.82) 1086.49,1675.31 1086.49,1534.76 U2.22@1084.65,1532.91
SYSREFRX_N: FMC_RX1.G10 R61.2 | length 3863.7
  Signals - L8 w4: v1(1238.99,1837.32) 1225.99,1850.32 1225.99,1858.13 1278.86,1911 4979,1911 4989,1901 4989,1895 v3(4984,1890)
  Bottom Layer - L10 w8: v3(4984,1890) FMC_RX1.G10@5009,1865
SYSREFRX_P: FMC_RX1.G9 R62.2 | length 3863.4
  Signals - L8 w4: v1(1204.99,1837.32) 1217.99,1850.32 1217.99,1861.45 1275.54,1919 4963,1919 v3(4984,1940)
  Bottom Layer - L10 w8: v3(4984,1940) FMC_RX1.G9@5009,1915
SYSREFTX_N: C37.2 R43.2 | length 630.8
  Top Layer L1 w8: R43.2@813.87,2130 795.87,2148 785.81,2148 769,2131.19 769,1945.6 931.23,1783.37 1017.25,1783.37 1037.93,1762.68 1037.93,1736.99 v1(1048.93,1725.99)
SYSREFTX_P: C35.2 R44.2 | length 636.3
  Top Layer L1 w8: R44.2@804.87,2164 779.19,2164 753,2137.81 753,1938.97 924.6,1767.37 1010.62,1767.37 1021.93,1756.05 v1(1021.93,1725.99)
SYSRF_N: C37.1 U2.20 | length 169.9
  Bottom Layer - L10 w8: U2.20@1045.28,1532.91 1043.43,1534.76 1043.43,1694.32 C37.1@1048.93,1699.82
SYSRF_P: C35.1 U2.19 | length 169.9
  Bottom Layer - L10 w8: C35.1@1021.93,1699.82 1027.43,1694.31 1027.43,1534.76 U2.19@1025.59,1532.91
TCRIT1: R16.1 R17.1 TCRIT1.1 U3.10 | length 266.6
  Top Layer L1 w9: U3.10@1621.08,777.07 1691.06,777.07 v1(1703.72,764.41) 1755.13,713 1776.28,713 TCRIT1.1@1836.28,653
TCRIT2: R15.1 TCRIT2.1 U3.11 | length 390.5
  Top Layer L1 w9: U3.11@1621.08,796.76 1666.28,796.76 v1(1668.28,798.76) 1691.06,798.76 R15.1@1703.72,811.41
  Signals - L6 w9: v1(1668.28,798.76) 1724.49,798.76 1798.25,725 TCRIT2.1@1939.5,725
TCRIT3: R14.1 TCRIT3.1 U3.14 | length 163.8
  Top Layer L1 w9: U3.14@1621.08,855.81 1703.72,855.81 TCRIT3.1@1703.72,937
TMST_N: R21.2 TMST-.1 | length 1399.8
  Bottom Layer - L10 w8: TMST-.1@100,2330.16 210,2330.16 228.2,2311.95 228.2,2120.03 246.58,2101.66 506.31,2101.66 824.6,1783.37 1070.26,1783.37 1101.5,1752.13 1101.5,1713.48 R21.2@1107,1707.98
TMST_P: R18.2 TMST+.1 | length 1400.3
  Bottom Layer - L10 w8: TMST+.1@100,1830.16 210,1830.16 228.2,1848.36 228.2,2067.28 246.58,2085.66 499.68,2085.66 817.98,1767.37 1063.63,1767.37 1085.5,1745.5 1085.5,1713.48 R18.2@1080,1707.98
U2-67: U2.67 | length 14.1
  Bottom Layer - L10 w9: 1025.59,1133 U2.67@1025.59,1147.09
U6-3: U6.3 | length 20.5
  Top Layer L1 w9: 1015.29,1953.27 U6.3@1015.29,1973.77
U6-4: U6.4 | length 20.5
  Top Layer L1 w9: 1034.98,1953.27 U6.4@1034.98,1973.77
U6-7: U6.7 | length 20.5
  Top Layer L1 w9: 1094.03,1953.27 U6.7@1094.03,1973.77
U6-8: U6.8 | length 20.5
  Top Layer L1 w9: 1113.72,1953.27 U6.8@1113.72,1973.77
U6-9: U6.9 | length 20.5
  Top Layer L1 w9: 1133.4,1953.27 U6.9@1133.4,1973.77
U6-15: U6.15 | length 20.5
  Top Layer L1 w9: 1251.51,1953.27 U6.15@1251.51,1973.77
U6-16: U6.16 | length 20.5
  Top Layer L1 w9: 1271.2,1953.27 U6.16@1271.2,1973.77
U6-22: U6.22 | length 20.5
  Top Layer L1 w9: U6.22@1296.79,2097.79 1317.29,2097.79
U6-23: U6.23 | length 20.5
  Top Layer L1 w9: U6.23@1296.79,2117.47 1317.29,2117.47
U6-27: U6.27 | length 20.5
  Top Layer L1 w9: U6.27@1296.79,2196.21 1317.29,2196.21
U6-28: U6.28 | length 20.5
  Top Layer L1 w9: U6.28@1296.79,2215.9 1317.29,2215.9
U6-29: U6.29 | length 20.5
  Top Layer L1 w9: U6.29@1296.79,2235.58 1317.29,2235.58
U6-30: U6.30 | length 20.5
  Top Layer L1 w9: U6.30@1296.79,2255.27 1317.29,2255.27
U6-32: U6.32 | length 20.5
  Top Layer L1 w9: U6.32@1296.79,2294.64 1317.29,2294.64
U6-37: U6.37 | length 20.5
  Top Layer L1 w9: U6.37@1192.46,2320.23 1192.46,2340.73
U6-38: U6.38 | length 20.5
  Top Layer L1 w9: U6.38@1172.77,2320.23 1172.77,2340.73
U6-40: U6.40 | length 20.5
  Top Layer L1 w9: U6.40@1133.4,2320.23 1133.4,2340.73
U6-41: U6.41 | length 20.5
  Top Layer L1 w9: U6.41@1113.72,2320.23 1113.72,2340.73
U6-43: U6.43 | length 20.5
  Top Layer L1 w9: U6.43@1074.35,2320.23 1074.35,2340.73
U6-44: U6.44 | length 20.5
  Top Layer L1 w9: U6.44@1054.66,2320.23 1054.66,2340.73
U6-49: U6.49 | length 20.5
  Top Layer L1 w9: 929.83,2294.64 U6.49@950.33,2294.64
U6-50: U6.50 | length 20.5
  Top Layer L1 w9: 929.83,2274.95 U6.50@950.33,2274.95
U6-51: U6.51 | length 20.5
  Top Layer L1 w9: 929.83,2255.27 U6.51@950.33,2255.27
U6-52: U6.52 | length 20.5
  Top Layer L1 w9: 929.83,2235.58 U6.52@950.33,2235.58
U6-54: U6.54 | length 20.5
  Top Layer L1 w9: 929.83,2196.21 U6.54@950.33,2196.21
U6-55: U6.55 | length 20.5
  Top Layer L1 w9: 929.83,2176.53 U6.55@950.33,2176.53
U6-58: U6.58 | length 20.5
  Top Layer L1 w9: 929.83,2117.47 U6.58@950.33,2117.47
U6-59: U6.59 | length 20.5
  Top Layer L1 w9: 929.83,2097.79 U6.59@950.33,2097.79
U6-60: U6.60 | length 20.5
  Top Layer L1 w9: 929.83,2078.1 U6.60@950.33,2078.1
U6-61: U6.61 | length 20.5
  Top Layer L1 w9: 929.83,2058.42 U6.61@950.33,2058.42
U6-62: U6.62 | length 20.5
  Top Layer L1 w9: 929.83,2038.73 U6.62@950.33,2038.73
U6-63: U6.63 | length 20.5
  Top Layer L1 w9: 929.83,2019.05 U6.63@950.33,2019.05
VADJ_RX: FMC_RX1.E39 FMC_RX1.F40 FMC_RX1.G39 FMC_RX1.H40 RR6.2 RR7.1 VADJ_RX.1 | length 2487.1
  Top Layer L1 w18: VADJ_RX.1@4659,2315 4959,2315 ; RR6.2@4959,2340 4959,2315 ; v1(4984,390) 4959,390 4959,2315
  Bottom Layer - L10 w18: FMC_RX1.H40@4959,365 v1(4984,390) FMC_RX1.G39@5009,415 v3(5034,390) FMC_RX1.F40@5059,365 v3(5084,390) FMC_RX1.E39@5109,415
VCC2: C103.1 L2.2 U6.17 | length 120.8
  Top Layer L1 w9: U6.17@1296.79,1999.36 v1(1331.87,1999.36)
  Bottom Layer - L10 w18: L2.2@1313,1932.5 C103.1@1313,1999.36 v1(1331.87,1999.36)
VCC3: C106.1 L4.2 U6.21 | length 100.4
  Top Layer L1 w9: U6.21@1296.79,2078.1 v1(1331.87,2078.1)
  Bottom Layer - L10 w18: C106.1@1313,2078.1 v1(1331.87,2078.1) 1363.23,2078.1 L4.2@1373.92,2067.42
VCC4: C111.1 L19.2 U6.26 | length 100.4
  Top Layer L1 w9: U6.26@1296.79,2176.53 v1(1331.87,2176.53)
  Bottom Layer - L10 w18: C111.1@1313,2176.53 v1(1331.87,2176.53) 1363.23,2176.53 L19.2@1373.92,2187.21
VCC6: C105.1 L3.2 U6.36 | length 112.2
  Top Layer L1 w9: U6.36@1212.14,2320.23 v1(1212.14,2355.31)
  Bottom Layer - L10 w18: L3.2@1170.95,2396.5 v1(1212.14,2355.31) C105.1@1212.14,2336.45
VCC9: C110.1 L5.2 U6.45 | length 95.1
  Top Layer L1 w9: U6.45@1034.98,2320.23 v1(1034.98,2355.31)
  Bottom Layer - L10 w18: C110.1@1034.98,2336.45 v1(1034.98,2355.31) L5.2@1034.98,2396.5
VCC11: C120.1 L21.2 U6.53 | length 93.7
  Top Layer L1 w9: v1(915.24,2215.9) U6.53@950.33,2215.9
  Bottom Layer - L10 w18: L21.2@875.5,2215.9 v1(915.24,2215.9) C120.1@934.11,2215.9
VCC12: C121.1 L22.2 U6.64 | length 93.7
  Top Layer L1 w9: v1(915.24,1999.36) U6.64@950.33,1999.36
  Bottom Layer - L10 w18: L22.2@875.5,1999.36 v1(915.24,1999.36) C121.1@934.11,1999.36
VIN_N: C5.1 C6.2 U2.9 | length 139.9
  Bottom Layer - L10 w8: v1(833.57,1343.66) 839.07,1338.16 968.63,1338.16 U2.9@970.47,1340
VIN_P: C1.1 C3.1 U2.8 | length 139.9
  Bottom Layer - L10 w8: v1(833.57,1316.66) 839.07,1322.16 968.63,1322.16 U2.8@970.47,1320.31
VIO_1P2VA: C39.1 C40.1 C41.2 C42.2 C43.2 C44.2 C45.2 C46.2 C47.2 C48.1 C177.1 C188.1 L15.2 U2.6 U2.11 U2.14 U2.17 U2.18 U2.21 U2.65 VA12.2 | length 654.1
  Top Layer L1 w16: C41.2@910.64,1280.94 v1(928.26,1280.94) ; C42.2@910.64,1379.37 v1(928.26,1379.37) ; C44.2@925.64,1497.48 v1(943.26,1497.48) ; v1(943.26,1438.43) C43.2@960.88,1438.43
  Top Layer L1 w18: v1(943.26,1497.48) 943.26,1560.13 v1(1005.91,1560.13) v1(1064.96,1560.13)
  Top Layer L1 w31.5: v1(2344.56,2406.01) v1(2406,2406.01) v1(2406,2341.5)
  Bottom Layer - L10 w9: v1(928.26,1280.94) U2.6@970.47,1280.94 ; v1(928.26,1379.37) U2.11@970.47,1379.37 ; v1(943.26,1438.43) U2.14@970.47,1438.43 ; v1(943.26,1497.48) U2.17@970.47,1497.48 ; U2.18@1005.91,1532.91 v1(1005.91,1560.13) ; v1(1064.96,1119.87) U2.65@1064.96,1147.09 ; U2.21@1064.96,1532.91 v1(1064.96,1560.13)
  Bottom Layer - L10 w16: v1(1005.91,1560.13) C45.2@1005.91,1577.75 ; C47.2@1064.96,1102.25 v1(1064.96,1119.87) ; v1(1064.96,1560.13) C46.2@1064.96,1577.75
VIO_1P2VD: C60.1 C61.1 C62.2 C63.2 C64.2 C65.2 C66.2 C67.2 C68.2 C69.2 C70.2 C71.2 C72.1 C189.1 C197.1 L16.2 NCO.2 NCO.4 NCO.6 RSV.3 U2.28 U2.31 U2.34 U2.37 U2.40 U2.43 U2.46 U2.49 U2.52 U2.55 VD12.2 | length 807.9
  Top Layer L1 w16: C71.2@1202.76,1542.5 v1(1202.76,1560.13)
  Top Layer L1 w18: v1(1261.81,1119.87) v1(1320.87,1119.87) ; v1(1261.81,1560.13) v1(1320.87,1560.13) 1368.25,1512.74 1368.25,1511.4 1383.51,1496.14 v1(1383.51,1458.11)
  Top Layer L1 w31.5: v1(2494,2292.5) v1(2494,2406.01)
  Bottom Layer - L10 w9: U2.28@1202.76,1532.91 v1(1202.76,1560.13) ; v1(1261.81,1119.87) U2.55@1261.81,1147.09 ; U2.31@1261.81,1532.91 v1(1261.81,1560.13) ; v1(1320.87,1119.87) U2.52@1320.87,1147.09 ; U2.34@1320.87,1532.91 v1(1320.87,1560.13) ; U2.49@1356.3,1221.89 v1(1383.51,1221.89) ; U2.46@1356.3,1280.94 v1(1383.51,1280.94) ; U2.43@1356.3,1340 v1(1383.51,1340) ; U2.40@1356.3,1399.06 v1(1383.51,1399.06) ; U2.37@1356.3,1458.11 v1(1383.51,1458.11)
  Bottom Layer - L10 w16: C62.2@1261.81,1102.25 v1(1261.81,1119.87) ; v1(1261.81,1560.13) C70.2@1261.81,1577.75 ; C63.2@1320.87,1102.25 v1(1320.87,1119.87) ; v1(1320.87,1560.13) C69.2@1320.87,1577.75 ; v1(1383.51,1221.89) C64.2@1401.13,1221.89 ; v1(1383.51,1280.94) C65.2@1401.13,1280.95 ; v1(1383.51,1340) C66.2@1401.13,1340 ; v1(1383.51,1399.06) C67.2@1401.13,1399.05 ; v1(1383.51,1458.11) C68.2@1401.13,1458.11
  other v1: 2494,2341.5
VIO_1P4: 1V2ADC_INT.1 C176.1 C190.1 C219.1 C221.1 C224.1 C225.1 L14.2 R83.1 | length 253.7
  Top Layer L1 w19.5: C219.1@2893.53,1090 v1(2936.85,1090)
  Top Layer L1 w31.5: v1(2936.85,1090) L14.2@2936.85,1143.5
  Bottom Layer - L10 w24: C190.1@2936.85,1084 v1@2936.85,1143.5
  Bottom Layer - L10 w51: R83.1@2888.18,2210.56 2888.18,2297.91 1V2ADC_INT.1@2895.27,2305
  other v1: 3033.32,1090 2936.85,1140 2888.68,1790 3033.32,1790
VIO_1P4V: C175.1 C182.1 C183.1 L12.2 L14.1 R82.2 | length 709
  Bottom Layer - L10 w10: C183.1@2936.85,1283 2953,1299.15 2953,1344.56 R82.2@3352,1743.56
  Bottom Layer - L10 w24: v1@2936.85,1206.5 C183.1@2936.85,1283
  other v1: 2936.85,1206.5 2936.85,1290 3352,1740
VIO_1P9V: C49.1 C50.1 C51.2 C52.2 C53.2 C54.2 C55.2 C56.2 C57.2 C58.2 C59.1 C130.1 C191.1 C202.1 L18.2 R39.1 R71.1 R80.1 R123.2 U2.4 U2.7 U2.10 U2.13 U2.24 U2.27 U2.60 U2.62 U12.15 VA19.2 | length 3113.2
  Top Layer L1 w13: U12.15@3762.24,429.5 3798.5,429.5 v1(3804,435)
  Top Layer L1 w15: v1(2777,2207) 2747,2177 2747,1990 2797,1940 R39.1@2828.44,1940 ; v1(3565,2207) 3535,2177 3535,1990 3585,1940 v1(3616.44,1940)
  Top Layer L1 w16: C51.2@910.64,1241.57 v1(928.26,1241.57) ; C54.2@910.64,1418.74 v1(928.26,1418.74) ; v1(943.26,1359.68) C53.2@960.88,1359.68
  Top Layer L1 w18: v1(943.26,1300.63) 953.58,1310.95 C52.2@963.57,1310.95
  Top Layer L1 w24: v1(3804,435) 3822,453 C130.1@3822,462.75 ; v1(3822,235.22) R123.2@3822,262.97
  Top Layer L1 w31.5: v1(4113.5,2602.93) 4113.5,2546.49 v1(4118.5,2541.49)
  Bottom Layer - L10 w9: v1(928.26,1241.57) U2.4@970.47,1241.57 ; v1(928.26,1418.74) U2.13@970.47,1418.74 ; v1(943.26,1300.63) U2.7@970.47,1300.63 ; v1(943.26,1359.68) U2.10@970.47,1359.68 ; v1(1124.02,1119.87) U2.62@1124.02,1147.09 ; U2.24@1124.02,1532.91 v1(1124.02,1560.13) ; v1(1163.39,1119.87) U2.60@1163.39,1147.09 ; U2.27@1183.07,1532.91 v1(1183.07,1575.13)
  Bottom Layer - L10 w16: C58.2@1124.02,1102.25 v1(1124.02,1119.87) ; v1(1124.02,1560.13) C55.2@1124.02,1577.75 ; C57.2@1163.39,1102.25 v1(1163.39,1119.87) ; v1(1183.07,1575.13) C56.2@1183.07,1592.75
  Bottom Layer - L10 w24: v1(3616.44,1940) 3645,1911.44 3645,1830 3616,1801 3616,1683.97 3599.61,1667.58 3599.61,1579.64 3614.25,1565 3684.97,1565 3699.61,1550.36 3699.61,651.39 3794,557 3794,445 v1(3804,435) 3822,417 v1(3822,235.22)
  other v1: 814,1103.87 3058.22,2631
VIO_2P25: 1V9INT.1 C199.1 C203.1 C222.1 C223.1 C226.1 C227.1 L20.2 R95.1 | length 258.5
  Top Layer L1 w19.5: v1(4151.15,1090) v1(4199.31,1090)
  Top Layer L1 w31.5: v1(4151.15,1090) L20.2@4151.15,1143.5
  Bottom Layer - L10 w24: C203.1@4151.15,1084 v1@4151.15,1143.5
  Bottom Layer - L10 w51: 1V9INT.1@3899,2269.07 3906.09,2261.98 R95.1@3993.44,2261.98
  other v1: 3810.69,1090 4151.15,1140 3810.69,1790 3987.32,1790
VIO_2P25V: C174.2 C180.1 C181.1 L11.1 L20.1 R81.1 | length 733.9
  Bottom Layer - L10 w10: R81.1@3688,1743.56 3698.56,1733 3707,1733 4135,1305 4135,1299.15 C181.1@4151.15,1283
  Bottom Layer - L10 w24: v1@4151.15,1206.5 C181.1@4151.15,1283
  other v1: 4151.15,1206.5 4151.15,1290 3688,1740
